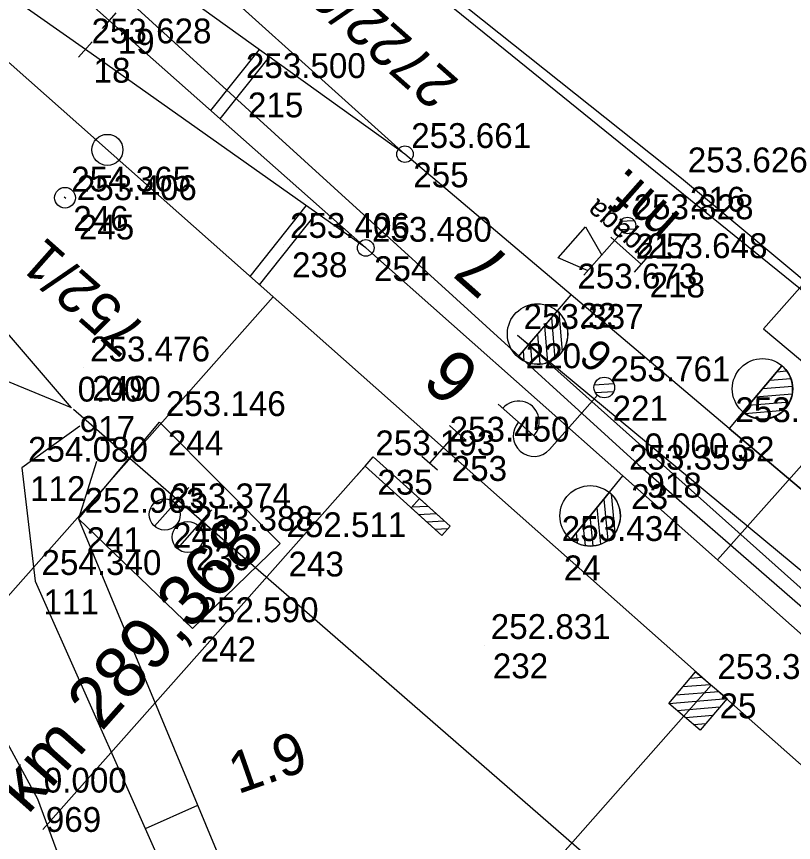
# Model space of a CAD drawing. Extents: x -496688 to -495455, y -1089309 to -1088026.
# Drawn here: x -495823.61 to -495786.03, y -1088787.38 to -1088747.46 of the extents above; entities that cross this region are included whole.
import ezdxf

# ---------------------------------------------------------------- set-up
doc = ezdxf.new("R2010")
doc.units = 0
for name, color, linetype in [('Vrstva 1', 7, 'Continuous'), ('Vrstva 17', 7, 'Continuous'), ('Vrstva 2', 7, 'Continuous'), ('Vrstva 25', 7, 'Continuous'), ('Vrstva 3', 7, 'Continuous'), ('Vrstva 33', 7, 'Continuous'), ('Vrstva 47', 7, 'Continuous'), ('Vrstva 48', 7, 'Continuous'), ('Vrstva 49', 7, 'Continuous'), ('Vrstva 53', 7, 'Continuous'), ('Vrstva 55', 7, 'Continuous'), ('Vrstva 57', 7, 'Continuous'), ('Vrstva 6', 7, 'Continuous'), ('Vrstva 60', 7, 'Continuous'), ('Vrstva 61', 7, 'Continuous'), ('Vrstva 7', 7, 'Continuous')]:
    doc.layers.add(name, color=color, linetype=linetype)

msp = doc.modelspace()

# ---------------------------------------------------------------- linework, layer by layer
at = {"layer": 'Vrstva 1'}
for p, q in [((-495736.793, -1088714.423), (-495789.71, -1088773.714)), ((-495787.48, -1088762.551), (-495764.119, -1088736.159)), ((-495811.199, -1088761.005), (-495868.035, -1088825.148)), ((-495787.48, -1088762.551), (-495777.73, -1088770.742))]:
    msp.add_line(p, q, dxfattribs=at)
for points in [[(-495794.281, -1088769.662), (-495806.718, -1088758.644), (-495819.114, -1088747.662), (-495828.107, -1088739.648), (-495840.608, -1088728.579), (-495852.984, -1088717.621), (-495860.029, -1088711.42), (-495872.461, -1088700.397), (-495884.955, -1088689.319), (-495893.533, -1088681.721), (-495913.179, -1088664.263), (-495947.105, -1088634.191), (-495952.116, -1088629.76), (-495964.613, -1088618.686), (-495984.901, -1088600.717), (-495997.336, -1088589.715), (-496002.819, -1088584.884), (-496021.751, -1088568.167), (-496024.418, -1088565.811), (-496062.504, -1088532.205), (-496086.773, -1088510.767), (-496106.199, -1088493.629), (-496127.249, -1088474.987), (-496164.633, -1088441.927)], [(-495784.233, -1088784.889), (-495790.007, -1088779.778), (-495797.538, -1088773.109), (-495802.96, -1088768.305), (-495829.435, -1088744.846), (-495841.88, -1088733.81), (-495854.312, -1088722.787), (-495863.196, -1088714.897), (-495875.701, -1088703.825), (-495888.14, -1088692.81), (-495895.834, -1088685.958), (-495903.705, -1088678.98), (-495916.136, -1088667.962), (-495923.285, -1088661.656)], [(-495597.746, -1088928.689), (-495606.602, -1088921.27), (-495628.038, -1088903.237), (-495662.023, -1088874.554), (-495695.238, -1088846.561), (-495728.41, -1088818.593), (-495747.734, -1088802.274), (-495769.843, -1088783.642), (-495779.5, -1088775.496), (-495789.139, -1088767.364), (-495796.782, -1088760.905), (-495804.819, -1088754.113), (-495818.323, -1088744.415), (-495826.921, -1088738.229), (-495840.608, -1088728.579), (-495854.107, -1088719.062), (-495862.093, -1088713.418), (-495875.701, -1088703.825)], [(-495806.718, -1088758.644), (-495820.279, -1088749.056), (-495828.327, -1088743.39), (-495841.88, -1088733.81)], [(-495804.819, -1088754.113), (-495817.188, -1088742.979)], [(-495761.135, -1088798.999), (-495776.818, -1088785.137), (-495794.281, -1088769.662)]]:
    msp.add_lwpolyline(points, dxfattribs=at)
at = {"layer": 'Vrstva 17'}
msp.add_lwpolyline([(-495820.615, -1088771.746), (-495816.688, -1088767.07), (-495810.853, -1088772.924), (-495815.101, -1088777.035), (-495820.615, -1088771.746)], dxfattribs=at)
at = {"layer": 'Vrstva 2'}
for p, q in [((-495819.446, -1088748.036), (-495818.782, -1088747.288)), ((-495820.611, -1088749.43), (-495819.947, -1088748.682)), ((-495797.451, -1088761.685), (-495796.782, -1088760.905)), ((-495797.452, -1088761.685), (-495799.352, -1088763.912)), ((-495799.352, -1088763.912), (-495797.451, -1088761.686)), ((-495797.451, -1088761.686), (-495797.452, -1088761.685)), ((-495797.372, -1088761.765), (-495797.222, -1088763.657)), ((-495797.728, -1088762.009), (-495797.572, -1088764.001)), ((-495798.073, -1088762.412), (-495797.933, -1088764.183)), ((-495798.417, -1088762.816), (-495798.304, -1088764.256)), ((-495798.761, -1088763.219), (-495798.682, -1088764.231)), ((-495799.106, -1088763.623), (-495799.069, -1088764.098)), ((-495788.478, -1088766.576), (-495786.59, -1088764.339)), ((-495786.59, -1088764.339), (-495788.477, -1088766.576)), ((-495787.177, -1088765.035), (-495786.165, -1088764.949)), ((-495786.835, -1088764.629), (-495786.36, -1088764.59)), ((-495787.519, -1088765.441), (-495786.08, -1088765.318)), ((-495787.862, -1088765.846), (-495786.092, -1088765.695)), ((-495788.203, -1088766.25), (-495786.213, -1088766.082)), ((-495788.386, -1088766.643), (-495786.494, -1088766.482)), ((-495788.479, -1088766.576), (-495789.139, -1088767.364)), ((-495788.477, -1088766.576), (-495788.478, -1088766.576)), ((-495794.935, -1088770.455), (-495794.281, -1088769.662)), ((-495794.935, -1088770.456), (-495796.789, -1088772.722)), ((-495796.789, -1088772.722), (-495794.935, -1088770.457)), ((-495794.935, -1088770.457), (-495794.935, -1088770.456)), ((-495794.852, -1088770.534), (-495794.664, -1088772.423)), ((-495795.205, -1088770.786), (-495795.007, -1088772.773)), ((-495795.54, -1088771.195), (-495795.364, -1088772.963)), ((-495795.875, -1088771.607), (-495795.733, -1088773.044)), ((-495796.211, -1088772.017), (-495796.111, -1088773.028)), ((-495796.548, -1088772.428), (-495796.5, -1088772.902))]:
    msp.add_line(p, q, dxfattribs=at)
for points in [[(-495796.782, -1088760.905), (-495804.819, -1088754.113), (-495817.188, -1088742.979)], [(-495804.819, -1088754.113), (-495818.323, -1088744.415)], [(-495794.281, -1088769.662), (-495806.718, -1088758.644), (-495819.114, -1088747.662)], [(-495806.718, -1088758.644), (-495820.279, -1088749.056)], [(-495789.139, -1088767.364), (-495779.5, -1088775.496), (-495769.843, -1088783.642)]]:
    msp.add_lwpolyline(points, dxfattribs=at)
for centre, radius in [((-495804.819, -1088754.113), 0.4), ((-495806.718, -1088758.644), 0.4), ((-495798.407, -1088762.806), 1.462), ((-495787.527, -1088765.452), 1.462), ((-495795.866, -1088771.596), 1.462)]:
    msp.add_circle(centre, radius, dxfattribs=at)
for centre, start, end in [((-495798.403, -1088762.799), 229.5239, 49.4848), ((-495787.534, -1088765.457), 229.8667, 49.8276), ((-495795.862, -1088771.589), 230.7137, 50.6746)]:
    msp.add_arc(centre, 1.464, start, end, dxfattribs=at)
at = {"layer": 'Vrstva 25'}
for p, q in [((-495794.713, -1088765.22), (-495795.669, -1088765.278)), ((-495795.514, -1088765.763), (-495797.835, -1088768.383)), ((-495794.727, -1088765.597), (-495795.605, -1088765.65)), ((-495798.359, -1088767.919), (-495800.305, -1088766.194))]:
    msp.add_line(p, q, dxfattribs=at)
msp.add_circle((-495795.182, -1088765.389), 0.5, dxfattribs=at)
msp.add_circle((-495795.182, -1088765.389), 0.5, dxfattribs=at)
for centre, start, end in [((-495799.323, -1088767.047), 317.7558, 139.161), ((-495798.583, -1088767.72), 138.4584, 318.4584)]:
    msp.add_arc(centre, 1, start, end, dxfattribs=at)
at = {"layer": 'Vrstva 3'}
for p, q in [((-495801.923, -1088767.888), (-495802.671, -1088767.225)), ((-495803.623, -1088769.053), (-495802.297, -1088767.557)), ((-495803.249, -1088769.385), (-495803.997, -1088768.722)), ((-495791.377, -1088779.847), (-495790.054, -1088779.739)), ((-495791.034, -1088779.443), (-495790.457, -1088779.395)), ((-495812.535, -1088805.234), (-495790.007, -1088779.778)), ((-495791.72, -1088780.252), (-495789.648, -1088780.082)), ((-495792.063, -1088780.657), (-495789.244, -1088780.425)), ((-495791.66, -1088780.999), (-495789.588, -1088780.829)), ((-495791.254, -1088781.343), (-495789.931, -1088781.234)), ((-495790.85, -1088781.685), (-495790.274, -1088781.638))]:
    msp.add_line(p, q, dxfattribs=at)
msp.add_lwpolyline([(-495790.77, -1088779.131), (-495789.244, -1088780.425), (-495790.538, -1088781.95), (-495792.063, -1088780.657)], close=True, dxfattribs=at)
msp.add_lwpolyline([(-495790.77, -1088779.131), (-495789.244, -1088780.425), (-495790.538, -1088781.95), (-495792.063, -1088780.657)], close=True, dxfattribs=at)
msp.add_lwpolyline([(-495790.77, -1088779.131), (-495789.244, -1088780.425), (-495790.538, -1088781.95), (-495792.063, -1088780.657), (-495790.77, -1088779.131)], dxfattribs=at)
msp.add_lwpolyline([(-495790.77, -1088779.131), (-495789.244, -1088780.425), (-495790.538, -1088781.95), (-495792.063, -1088780.657), (-495790.77, -1088779.131)], dxfattribs=at)
at = {"layer": 'Vrstva 33'}
for p, q in [((-495793.735, -1088757.331), (-495794.416, -1088757.372)), ((-495797.418, -1088759.122), (-495796.092, -1088757.625)), ((-495796.092, -1088757.625), (-495795.301, -1088758.994)), ((-495793.703, -1088757.73), (-495794.397, -1088757.772)), ((-495796.163, -1088759.967), (-495794.311, -1088757.873)), ((-495795.964, -1088759.743), (-495797.418, -1088759.122))]:
    msp.add_line(p, q, dxfattribs=at)
msp.add_circle((-495794.063, -1088757.558), 0.401, dxfattribs=at)
msp.add_circle((-495794.063, -1088757.558), 0.401, dxfattribs=at)
at = {"layer": 'Vrstva 47'}
for p, q in [((-495816.936, -1088772.09), (-495815.278, -1088770.219)), ((-495815.823, -1088773.182), (-495814.165, -1088771.311))]:
    msp.add_line(p, q, dxfattribs=at)
for centre in [(-495816.439, -1088771.529), (-495815.326, -1088772.621)]:
    msp.add_circle(centre, 0.75, dxfattribs=at)
at = {"layer": 'Vrstva 48'}
msp.add_line((-495814.848, -1088785.588), (-495817.378, -1088786.715), dxfattribs=at)
at = {"layer": 'Vrstva 49'}
for p, q in [((-495819.735, -1088768.969), (-495820.615, -1088771.746)), ((-495820.615, -1088771.746), (-495801.946, -1088816.553))]:
    msp.add_line(p, q, dxfattribs=at)
for points in [[(-495763.13, -1088778.611), (-495765.306, -1088777.077), (-495791.441, -1088755.289), (-495814.323, -1088737.085), (-495838.033, -1088710.491), (-495852.843, -1088691.248), (-495865.843, -1088664.821), (-495876.068, -1088642.052), (-495881.546, -1088626.667), (-495882.811, -1088621.688)], [(-495602.051, -1088936.915), (-495632.866, -1088909.798), (-495666.623, -1088879.883), (-495697.534, -1088851.693), (-495731.165, -1088822.519), (-495756.889, -1088800.018), (-495772.95, -1088786.427), (-495799.381, -1088762.858)], [(-495799.381, -1088762.858), (-495772.047, -1088785.51), (-495755.904, -1088798.889), (-495729.536, -1088821.329), (-495698.379, -1088848.259), (-495665.143, -1088876.648), (-495631.905, -1088905.647), (-495602.908, -1088933.77)], [(-495820.542, -1088767.266), (-495823.352, -1088769.277), (-495822.701, -1088774.752), (-495813.353, -1088795.762), (-495809.36, -1088807.978), (-495804.929, -1088829.819), (-495802.497, -1088849.398)]]:
    msp.add_lwpolyline(points, dxfattribs=at)
at = {"layer": 'Vrstva 53'}
msp.add_line((-495816.57, -1088735.63), (-495778.36, -1088766.56), dxfattribs=at)
msp.add_lwpolyline([(-495820.95, -1088766.37), (-495836.28, -1088760.05), (-495822.59, -1088785.27), (-495810.8, -1088817.2), (-495805.63, -1088839.06), (-495801.74, -1088870.1), (-495801.67, -1088898.42), (-495801.94, -1088953.23), (-495800.51, -1088960.04), (-495800.3, -1088973.88), (-495761.53, -1088987.72), (-495761.24, -1088987.38), (-495760.41, -1088988.12), (-495744.16, -1088993.92), (-495645.99, -1088956.12), (-495627.19, -1088948.89), (-495666.59, -1088906.58), (-495728.02, -1088847.18), (-495820.854, -1088766.454)], dxfattribs=at)
at = {"layer": 'Vrstva 55'}
msp.add_line((-495820.95, -1088766.37), (-495861.51, -1088719.25), dxfattribs=at)
msp.add_lwpolyline([(-495876.99, -1088692.49), (-495855.07, -1088713.16), (-495793.54, -1088769.11), (-495671.98, -1088874.82), (-495634.71, -1088905.31), (-495611.24, -1088924.48), (-495609.02, -1088926.3), (-495602.5, -1088931.63)], dxfattribs=at)
at = {"layer": 'Vrstva 6'}
for p, q in [((-495794.87, -1088758.124), (-495793.388, -1088759.437)), ((-495793.72, -1088759.811), (-495793.056, -1088759.063)), ((-495822.331, -1088786.756), (-495806.552, -1088768.968)), ((-495806.753, -1088769.191), (-495807.155, -1088769.637)), ((-495804.124, -1088770.755), (-495804.526, -1088771.2)), ((-495804.135, -1088770.768), (-495804.111, -1088770.766)), ((-495804.124, -1088770.755), (-495804.124, -1088770.755)), ((-495804.491, -1088771.162), (-495803.717, -1088771.122)), ((-495804.171, -1088771.521), (-495803.324, -1088771.477)), ((-495803.777, -1088771.876), (-495802.93, -1088771.832)), ((-495803.383, -1088772.232), (-495802.732, -1088772.198))]:
    msp.add_line(p, q, dxfattribs=at)
msp.add_lwpolyline([(-495806.351, -1088768.745), (-495802.639, -1088772.094), (-495803.041, -1088772.54), (-495806.753, -1088769.191), (-495806.351, -1088768.745)], dxfattribs=at)
msp.add_lwpolyline([(-495803.041, -1088772.54), (-495804.526, -1088771.2), (-495804.124, -1088770.755), (-495802.639, -1088772.094)], close=True, dxfattribs=at)
at = {"layer": 'Vrstva 60'}
for p, q in [((-495819.114, -1088747.662), (-495819.114, -1088747.662)), ((-495819.114, -1088747.662), (-495819.114, -1088747.662)), ((-495820.279, -1088749.056), (-495820.279, -1088749.056)), ((-495820.279, -1088749.056), (-495820.279, -1088749.056)), ((-495812.815, -1088750.732), (-495812.815, -1088750.732)), ((-495812.815, -1088750.732), (-495812.815, -1088750.732)), ((-495804.819, -1088754.113), (-495804.819, -1088754.113)), ((-495804.819, -1088754.113), (-495804.819, -1088754.113)), ((-495791.441, -1088755.289), (-495791.441, -1088755.289)), ((-495791.441, -1088755.289), (-495791.441, -1088755.289)), ((-495821.263, -1088756.218), (-495821.263, -1088756.218)), ((-495821.263, -1088756.218), (-495821.263, -1088756.218)), ((-495820.991, -1088756.635), (-495820.991, -1088756.635)), ((-495820.991, -1088756.635), (-495820.991, -1088756.635)), ((-495794.063, -1088757.558), (-495794.063, -1088757.558)), ((-495794.063, -1088757.558), (-495794.063, -1088757.558)), ((-495810.681, -1088758.459), (-495810.681, -1088758.459)), ((-495810.681, -1088758.459), (-495810.681, -1088758.459)), ((-495806.718, -1088758.644), (-495806.718, -1088758.644)), ((-495806.718, -1088758.644), (-495806.718, -1088758.644)), ((-495793.388, -1088759.437), (-495793.388, -1088759.437)), ((-495793.388, -1088759.437), (-495793.388, -1088759.437)), ((-495796.782, -1088760.905), (-495796.782, -1088760.905)), ((-495796.782, -1088760.905), (-495796.782, -1088760.905)), ((-495799.381, -1088762.858), (-495799.381, -1088762.858)), ((-495799.381, -1088762.858), (-495799.381, -1088762.858)), ((-495820.349, -1088764.427), (-495820.349, -1088764.427)), ((-495820.349, -1088764.427), (-495820.349, -1088764.427)), ((-495795.182, -1088765.389), (-495795.182, -1088765.389)), ((-495795.182, -1088765.389), (-495795.182, -1088765.389)), ((-495820.95, -1088766.37), (-495820.95, -1088766.37)), ((-495820.95, -1088766.37), (-495820.95, -1088766.37)), ((-495816.688, -1088767.07), (-495816.688, -1088767.07)), ((-495816.688, -1088767.07), (-495816.688, -1088767.07)), ((-495789.139, -1088767.364), (-495789.139, -1088767.364)), ((-495789.139, -1088767.364), (-495789.139, -1088767.364)), ((-495802.96, -1088768.305), (-495802.96, -1088768.305)), ((-495802.96, -1088768.305), (-495802.96, -1088768.305)), ((-495806.552, -1088768.968), (-495806.552, -1088768.968)), ((-495806.552, -1088768.968), (-495806.552, -1088768.968)), ((-495823.352, -1088769.277), (-495823.352, -1088769.277)), ((-495823.352, -1088769.277), (-495823.352, -1088769.277)), ((-495793.54, -1088769.11), (-495793.54, -1088769.11)), ((-495793.54, -1088769.11), (-495793.54, -1088769.11)), ((-495794.281, -1088769.662), (-495794.281, -1088769.662)), ((-495794.281, -1088769.662), (-495794.281, -1088769.662)), ((-495820.615, -1088771.746), (-495820.615, -1088771.746)), ((-495820.615, -1088771.746), (-495820.615, -1088771.746)), ((-495816.439, -1088771.529), (-495816.439, -1088771.529)), ((-495816.439, -1088771.529), (-495816.439, -1088771.529)), ((-495815.326, -1088772.621), (-495815.326, -1088772.621)), ((-495815.326, -1088772.621), (-495815.326, -1088772.621)), ((-495810.853, -1088772.924), (-495810.853, -1088772.924)), ((-495810.853, -1088772.924), (-495810.853, -1088772.924)), ((-495797.538, -1088773.109), (-495797.538, -1088773.109)), ((-495797.538, -1088773.109), (-495797.538, -1088773.109)), ((-495822.701, -1088774.752), (-495822.701, -1088774.752)), ((-495822.701, -1088774.752), (-495822.701, -1088774.752)), ((-495815.101, -1088777.035), (-495815.101, -1088777.035)), ((-495815.101, -1088777.035), (-495815.101, -1088777.035)), ((-495800.972, -1088777.846), (-495800.972, -1088777.846)), ((-495800.972, -1088777.846), (-495800.972, -1088777.846)), ((-495790.007, -1088779.778), (-495790.007, -1088779.778)), ((-495790.007, -1088779.778), (-495790.007, -1088779.778)), ((-495822.59, -1088785.27), (-495822.59, -1088785.27)), ((-495822.59, -1088785.27), (-495822.59, -1088785.27))]:
    msp.add_line(p, q, dxfattribs=at)
at = {"layer": 'Vrstva 7'}
for p, q in [((-495814.214, -1088752.003), (-495811.861, -1088749.056)), ((-495813.764, -1088752.401), (-495811.372, -1088749.407)), ((-495821.226, -1088756.251), (-495821.3, -1088756.185)), ((-495812.305, -1088760.025), (-495809.597, -1088756.608)), ((-495811.855, -1088760.423), (-495809.106, -1088756.956))]:
    msp.add_line(p, q, dxfattribs=at)
for centre, radius in [((-495819.213, -1088753.904), 0.75), ((-495821.263, -1088756.218), 0.5)]:
    msp.add_circle(centre, radius, dxfattribs=at)

# ---------------------------------------------------------------- texts
at = {"layer": 'Vrstva 2'}
for s, rotation, p in [('7', 138.4565, (-495799.524, -1088759.338)), ('6', 138.4738, (-495801.039, -1088764.569))]:
    msp.add_text(s, height=2.5, rotation=rotation, dxfattribs=at).set_placement(p)
at = {"layer": 'Vrstva 25'}
msp.add_text('6', height=1.5, rotation=138.4583, dxfattribs=at).set_placement((-495794.653, -1088763.67))
at = {"layer": 'Vrstva 33'}
msp.add_text('mf.', height=2, rotation=138.4564, dxfattribs=at).set_placement((-495791.4, -1088757.107))
at = {"layer": 'Vrstva 48'}
msp.add_text('1.9', height=2, rotation=19.2708, dxfattribs=at).set_placement((-495812.9, -1088785.058))
at = {"layer": 'Vrstva 57'}
for s, rotation, p in [('2722/6', 138.5264, (-495802.139, -1088750.586)), ('752/1', 138.4565, (-495817.207, -1088762.521))]:
    msp.add_text(s, height=2, rotation=rotation, dxfattribs=at).set_placement(p)
at = {"layer": 'Vrstva 6'}
for s, height, rotation, p in [('qqaqa', 1, 138.4583, (-495792.725, -1088758.689)), ('km 289,368', 2.5, 48.4246, (-495823.067, -1088786.079))]:
    msp.add_text(s, height=height, rotation=rotation, dxfattribs=at).set_placement(p)
at = {"layer": 'Vrstva 60'}
for s, p in [('19', (-495818.714, -1088749.262)), ('19', (-495818.714, -1088749.262)), ('18', (-495819.879, -1088750.656)), ('18', (-495819.879, -1088750.656)), ('215', (-495812.415, -1088752.332)), ('215', (-495812.415, -1088752.332)), ('255', (-495804.419, -1088755.713)), ('255', (-495804.419, -1088755.713)), ('216', (-495791.041, -1088756.889)), ('216', (-495791.041, -1088756.889)), ('246', (-495820.863, -1088757.818)), ('246', (-495820.863, -1088757.818)), ('245', (-495820.591, -1088758.235)), ('245', (-495820.591, -1088758.235)), ('217', (-495793.663, -1088759.158)), ('217', (-495793.663, -1088759.158)), ('238', (-495810.281, -1088760.059)), ('238', (-495810.281, -1088760.059)), ('254', (-495806.318, -1088760.244)), ('254', (-495806.318, -1088760.244)), ('218', (-495792.988, -1088761.037)), ('218', (-495792.988, -1088761.037)), ('22', (-495796.382, -1088762.505)), ('22', (-495796.382, -1088762.505)), ('220', (-495798.981, -1088764.458)), ('220', (-495798.981, -1088764.458)), ('249', (-495819.949, -1088766.027)), ('249', (-495819.949, -1088766.027)), ('221', (-495794.782, -1088766.989)), ('221', (-495794.782, -1088766.989)), ('917', (-495820.55, -1088767.97)), ('917', (-495820.55, -1088767.97)), ('244', (-495816.288, -1088768.67)), ('244', (-495816.288, -1088768.67)), ('32', (-495788.739, -1088768.964)), ('32', (-495788.739, -1088768.964)), ('253', (-495802.56, -1088769.905)), ('253', (-495802.56, -1088769.905)), ('235', (-495806.152, -1088770.568)), ('235', (-495806.152, -1088770.568)), ('112', (-495822.952, -1088770.877)), ('112', (-495822.952, -1088770.877)), ('918', (-495793.14, -1088770.71)), ('918', (-495793.14, -1088770.71)), ('23', (-495793.881, -1088771.262)), ('23', (-495793.881, -1088771.262)), ('241', (-495820.215, -1088773.346)), ('241', (-495820.215, -1088773.346)), ('240', (-495816.039, -1088773.129)), ('240', (-495816.039, -1088773.129)), ('239', (-495814.926, -1088774.221)), ('239', (-495814.926, -1088774.221)), ('243', (-495810.453, -1088774.524)), ('243', (-495810.453, -1088774.524)), ('24', (-495797.138, -1088774.709)), ('24', (-495797.138, -1088774.709)), ('111', (-495822.301, -1088776.352)), ('111', (-495822.301, -1088776.352)), ('242', (-495814.701, -1088778.635)), ('242', (-495814.701, -1088778.635)), ('232', (-495800.572, -1088779.446)), ('232', (-495800.572, -1088779.446)), ('25', (-495789.607, -1088781.378)), ('25', (-495789.607, -1088781.378)), ('969', (-495822.19, -1088786.87)), ('969', (-495822.19, -1088786.87))]:
    msp.add_text(s, height=1.2, dxfattribs=at).set_placement(p)
at = {"layer": 'Vrstva 61'}
for s, p in [('253.628', (-495819.979, -1088748.756)), ('253.628', (-495819.979, -1088748.756)), ('253.500', (-495812.515, -1088750.432)), ('253.500', (-495812.515, -1088750.432)), ('253.661', (-495804.519, -1088753.813)), ('253.661', (-495804.519, -1088753.813)), ('253.626', (-495791.141, -1088754.989)), ('253.626', (-495791.141, -1088754.989)), ('254.365', (-495820.963, -1088755.918)), ('254.365', (-495820.963, -1088755.918)), ('253.406', (-495820.691, -1088756.335)), ('253.406', (-495820.691, -1088756.335)), ('253.828', (-495793.763, -1088757.258)), ('253.828', (-495793.763, -1088757.258)), ('253.406', (-495810.381, -1088758.159)), ('253.406', (-495810.381, -1088758.159)), ('253.480', (-495806.418, -1088758.344)), ('253.480', (-495806.418, -1088758.344)), ('253.648', (-495793.088, -1088759.137)), ('253.648', (-495793.088, -1088759.137)), ('253.673', (-495796.482, -1088760.605)), ('253.673', (-495796.482, -1088760.605)), ('253.337', (-495799.081, -1088762.558)), ('253.337', (-495799.081, -1088762.558)), ('253.476', (-495820.049, -1088764.127)), ('253.476', (-495820.049, -1088764.127)), ('253.761', (-495794.882, -1088765.089)), ('253.761', (-495794.882, -1088765.089)), ('0.000', (-495820.65, -1088766.07)), ('0.000', (-495820.65, -1088766.07)), ('253.146', (-495816.388, -1088766.77)), ('253.146', (-495816.388, -1088766.77)), ('253.701', (-495788.839, -1088767.064)), ('253.701', (-495788.839, -1088767.064)), ('253.450', (-495802.66, -1088768.005)), ('253.450', (-495802.66, -1088768.005)), ('254.080', (-495823.052, -1088768.977)), ('254.080', (-495823.052, -1088768.977)), ('253.193', (-495806.252, -1088768.668)), ('253.193', (-495806.252, -1088768.668)), ('0.000', (-495793.24, -1088768.81)), ('0.000', (-495793.24, -1088768.81)), ('253.359', (-495793.981, -1088769.362)), ('253.359', (-495793.981, -1088769.362)), ('253.374', (-495816.139, -1088771.229)), ('253.374', (-495816.139, -1088771.229)), ('252.963', (-495820.315, -1088771.446)), ('252.963', (-495820.315, -1088771.446)), ('253.388', (-495815.026, -1088772.321)), ('253.388', (-495815.026, -1088772.321)), ('252.511', (-495810.553, -1088772.624)), ('252.511', (-495810.553, -1088772.624)), ('253.434', (-495797.238, -1088772.809)), ('253.434', (-495797.238, -1088772.809)), ('254.340', (-495822.401, -1088774.452)), ('254.340', (-495822.401, -1088774.452)), ('252.590', (-495814.801, -1088776.735)), ('252.590', (-495814.801, -1088776.735)), ('252.831', (-495800.672, -1088777.546)), ('252.831', (-495800.672, -1088777.546)), ('253.371', (-495789.707, -1088779.478)), ('253.371', (-495789.707, -1088779.478)), ('0.000', (-495822.29, -1088784.97)), ('0.000', (-495822.29, -1088784.97))]:
    msp.add_text(s, height=1.2, dxfattribs=at).set_placement(p)

doc.saveas('drawing.dxf')
